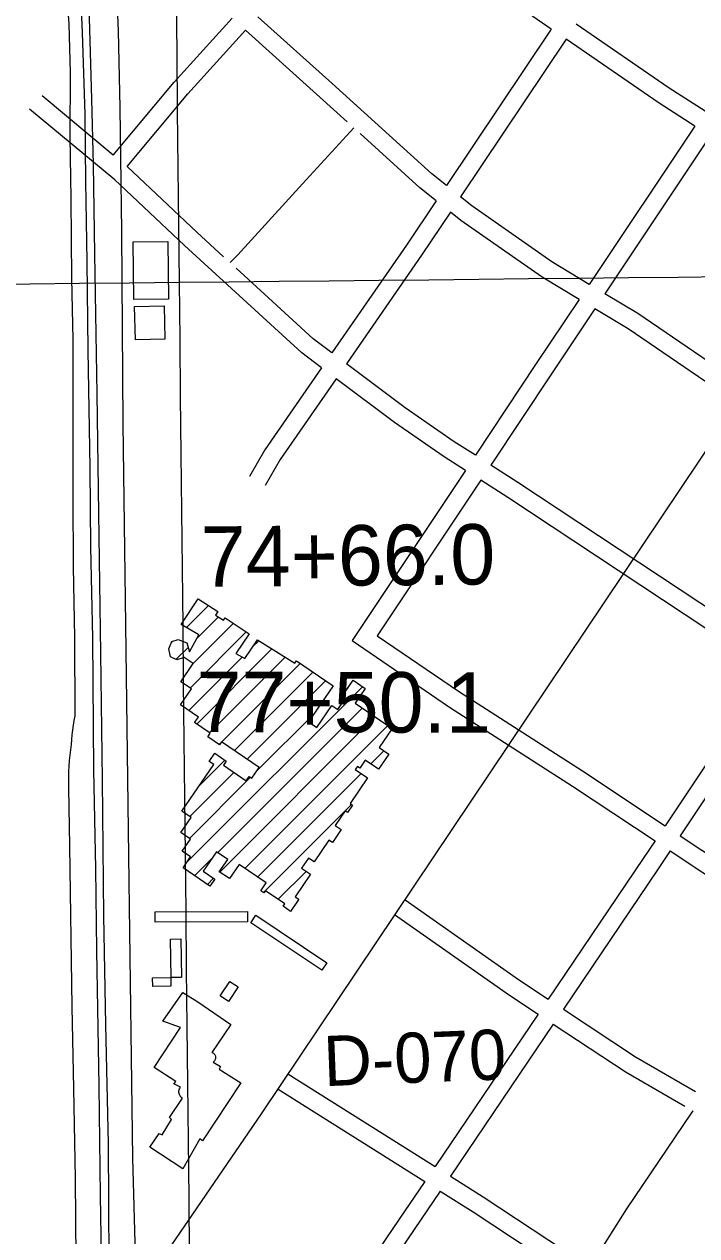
# Model space of a CAD drawing. Extents: x 3651524 to 3689615, y 505651 to 531377.
# Drawn here: x 3660662 to 3661774, y 521661 to 523666 of the extents above; entities that cross this region are included whole.
import ezdxf

# ---------------------------------------------------------------- set-up
doc = ezdxf.new("R2010")
doc.units = 0
for name, color, linetype in [('V-BLDG-OTLN', 7, 'Continuous'), ('V-GRID-MAJR', 7, 'Continuous'), ('V-RAIL-TRAK', 7, 'Continuous'), ('V-RIVR-RANG-IDEN', 7, 'Continuous'), ('V-ROAD-CNTR', 7, 'Continuous'), ('V-SURV-IDEN', 7, 'Continuous')]:
    doc.layers.add(name, color=color, linetype=linetype)

msp = doc.modelspace()

# ---------------------------------------------------------------- linework, layer by layer
at = {"layer": 'V-BLDG-OTLN'}
for p, q in [((3660930.25, 522667.432), (3660966.629, 522703.812)), ((3660940.957, 522607.429), (3661007.926, 522674.398)), ((3660947.036, 522648.864), (3660982.984, 522684.811)), ((3660936.162, 522567.278), (3661029.151, 522660.268)), ((3660905.354, 522642.537), (3660907.412, 522644.595)), ((3660912.74, 522614.567), (3660932.78, 522634.607)), ((3661040.092, 522635.853), (3661049.846, 522645.607)), ((3660934.234, 522529.996), (3661022.552, 522618.313)), ((3660947.236, 522507.642), (3661071.585, 522631.99)), ((3660968.25, 522493.3), (3661093.323, 522618.373)), ((3660988.43, 522478.125), (3661118.28, 522607.975)), ((3661009.443, 522463.783), (3661139.292, 522593.632)), ((3661030.457, 522449.441), (3661160.305, 522579.29)), ((3660930.849, 522279.123), (3661221.244, 522569.517)), ((3660982.092, 522295.01), (3661220.882, 522533.8)), ((3660985.322, 522262.885), (3661241.895, 522519.458)), ((3661045.955, 522429.584), (3661142.284, 522525.913)), ((3661026.568, 522268.776), (3661262.909, 522505.117)), ((3660983.921, 522473.616), (3660986.898, 522476.593)), ((3661234.878, 522441.73), (3661256.591, 522463.444)), ((3660951.529, 522405.869), (3660993.588, 522447.928)), ((3660934.93, 522318.559), (3661036.105, 522419.734)), ((3660935.626, 522354.61), (3661008.745, 522427.729)), ((3661047.58, 522254.433), (3661219.009, 522425.861)), ((3661192.678, 522364.176), (3661202.934, 522374.431)), ((3661057.399, 522228.896), (3661192.141, 522363.638)), ((3660943.722, 522256.641), (3660972.28, 522285.199)), ((3660964.735, 522242.298), (3660975.099, 522252.663)), ((3661081.547, 522217.689), (3661127.851, 522263.993))]:
    msp.add_line(p, q, dxfattribs=at)
for points in [[(3660899.25, 523306.151), (3660900.525, 523210.829), (3660843.259, 523210.063), (3660841.985, 523305.385)], [(3660893.224, 523199.71), (3660894.619, 523144.637), (3660845.84, 523143.405), (3660844.443, 523198.475)], [(3661112.07, 522612.213), (3661172.864, 522570.718), (3661132.212, 522511.156), (3661145.929, 522501.795), (3661170.777, 522538.2), (3661180.247, 522531.737), (3661189.623, 522545.475), (3661184.329, 522549.089), (3661205.571, 522580.213), (3661225.621, 522566.53), (3661208.874, 522541.995), (3661270.032, 522500.255), (3661248.622, 522468.883), (3661264.562, 522458.004), (3661247.551, 522433.08), (3661225.875, 522447.875), (3661217.042, 522434.934), (3661212.989, 522437.701), (3661209.388, 522432.427), (3661229.631, 522418.611), (3661200.576, 522376.041), (3661204.643, 522373.264), (3661196.611, 522361.492), (3661192.562, 522364.255), (3661176.018, 522340.017), (3661186.199, 522333.07), (3661171.613, 522311.701), (3661165.672, 522315.757), (3661141.061, 522279.697), (3661131.968, 522285.905), (3661120.456, 522269.04), (3661135.005, 522259.111), (3661109.675, 522221.997), (3661115.891, 522217.754), (3661102.19, 522197.677), (3661089.82, 522206.119), (3661092.579, 522210.16), (3661060.603, 522231.983), (3661058.148, 522228.385), (3661052.936, 522231.942), (3661061.705, 522244.791), (3661017.057, 522275.268), (3661001.205, 522252.043), (3660984.52, 522263.432), (3660998.453, 522283.845), (3660979.967, 522296.46), (3660958.027, 522264.317), (3660977.176, 522251.245), (3660969.058, 522239.348), (3660924.471, 522269.781), (3660936.97, 522288.088), (3660923.271, 522297.439), (3660936.81, 522317.276), (3660920.872, 522328.153), (3660937.881, 522353.071), (3660922.607, 522363.493), (3660975.185, 522440.529), (3660967.561, 522445.733), (3660976.854, 522459.35), (3660995.841, 522446.39), (3660991.254, 522439.669), (3661029.048, 522413.87), (3661034.02, 522421.157), (3661038.239, 522418.277), (3661050.275, 522435.915), (3660988.098, 522478.351), (3660984.565, 522473.176), (3660965.32, 522486.312), (3660969.504, 522492.444), (3660943.701, 522510.054), (3660949.979, 522519.25), (3660920.446, 522539.406), (3660938.42, 522565.737), (3660920.739, 522577.804), (3660941.168, 522607.738), (3660926.562, 522617.705), (3660914.04, 522613.917), (3660903.802, 522619.037), (3660900.89, 522632.113), (3660906.043, 522644.145), (3660916.434, 522647.557), (3660930.705, 522641.917), (3660934.932, 522627.022), (3660950.706, 522655.485), (3660921.366, 522672.621), (3660949.507, 522714.789), (3660981.925, 522694.006), (3660978.222, 522687.784), (3660991.549, 522679.465), (3660994.314, 522683.459), (3661033.82, 522657.16), (3661011.683, 522624.314), (3661026.805, 522615.965), (3661047.564, 522647.037), (3661109.403, 522608.301)], [(3661031.151, 522180.699), (3660878.436, 522179.804), (3660878.337, 522196.727), (3661031.051, 522197.62)], [(3661154.131, 522100.381), (3661036.507, 522178.809), (3661044.809, 522191.261), (3661162.438, 522112.832)], [(3660905.111, 522088.164), (3660903.542, 522151.966), (3660920.616, 522152.383), (3660922.183, 522088.582)], [(3660904.406, 522073.806), (3660874.309, 522073.437), (3660874.133, 522087.966), (3660904.23, 522088.328)], [(3661015.768, 522072.735), (3660999.626, 522048.769), (3660985.991, 522057.952), (3661002.133, 522081.92)], [(3661003.802, 522010.578), (3660972.283, 521964.49), (3660973.582, 521963.914), (3660974.772, 521963.142), (3660975.824, 521962.194), (3660976.717, 521961.09), (3660977.428, 521959.859), (3660977.934, 521958.534), (3660978.229, 521957.144), (3660978.3, 521955.726), (3660978.149, 521954.313), (3660977.778, 521952.941), (3660977.198, 521951.645), (3660976.422, 521950.455), (3660975.47, 521949.402), (3660974.364, 521948.511), (3660986.634, 521941.208), (3660984.19, 521936.528), (3661019.811, 521914.052), (3660956.71, 521818.33), (3660952.041, 521821.365), (3660924.002, 521771.673), (3660869.721, 521807.467), (3660884.885, 521830.229), (3660890.156, 521827.773), (3660905.371, 521853.486), (3660901.879, 521856.499), (3660923.707, 521888.589), (3660922.349, 521889.496), (3660921.124, 521890.579), (3660920.059, 521891.816), (3660919.166, 521893.184), (3660918.468, 521894.661), (3660917.972, 521896.216), (3660917.69, 521897.825), (3660917.624, 521899.458), (3660917.784, 521901.084), (3660918.157, 521902.675), (3660918.738, 521904.201), (3660919.521, 521905.634), (3660920.489, 521906.949), (3660909.367, 521912.46), (3660912.392, 521916.54), (3660876.781, 521939.604), (3660920.104, 522005.564), (3660891.359, 522016.11), (3660924.077, 522063.359), (3660948.791, 522048.202)]]:
    msp.add_lwpolyline(points, close=True, dxfattribs=at)
at = {"layer": 'V-GRID-MAJR'}
for points in [[(3661045.474, 511119.283), (3660982.023, 517177.978), (3660918.553, 523238.605), (3660855.082, 529299.245), (3660855.062, 529301.164)], [(3655639.78, 523183.706), (3660918.553, 523238.605), (3666197.317, 523294.271), (3671476.073, 523350.705), (3676754.821, 523407.907), (3682033.561, 523465.877), (3687312.292, 523524.615)]]:
    msp.add_spline(points, degree=3, dxfattribs=at)
at = {"layer": 'V-RAIL-TRAK'}
for points in [[(3660802.488, 521616.582), (3660801.238, 521813.224), (3660797.038, 522009.92), (3660793.737, 522190.656), (3660791.218, 522415.664), (3660788.418, 522624.734), (3660785.434, 522856.834), (3660782.425, 523054.099), (3660778.839, 523285.622), (3660776.726, 523433.27), (3660773.914, 523541.374), (3660768.47, 523734.547)], [(3660755.14, 523715.298), (3660757.565, 523652.079), (3660762.261, 523516.782), (3660763.24, 523405.168), (3660765.626, 523272.865), (3660767.17, 523126.404), (3660770.221, 522931.5), (3660771.446, 522800.399), (3660774.7, 522650.367), (3660776.732, 522431.272), (3660779.767, 522268.843), (3660781.5, 522133.009), (3660785.211, 521908.571), (3660787.33, 521727.856), (3660790.837, 521525.267)]]:
    msp.add_lwpolyline(points, dxfattribs=at)
at = {"layer": 'V-ROAD-CNTR'}
for points in [[(3660141.295, 529270.676), (3660140.146, 529257.885), (3660207.54, 528672.889), (3660264.536, 528198.301), (3660307.434, 527853.775), (3660381.584, 527230.666), (3660444.851, 526759.634), (3660523.843, 526091.959), (3660593.844, 525547.214), (3660619.118, 525319.853), (3660656.441, 525032.649), (3660719.252, 524520.83), (3660759.714, 524185.351), (3660783.113, 524013.914), (3660804.031, 523834.787), (3660814.113, 523733.801), (3660817.382, 523654.494), (3660819.82, 523527.387), (3660822.74, 523322.401), (3660825.188, 523004.512), (3660829.644, 522672.085), (3660834.768, 522247.179), (3660840.69, 521789.439), (3660851.979, 521389.387)], [(3662939.923, 524671.627), (3662283.158, 523697.88), (3661053.666, 521862.612), (3660883.673, 521614.704), (3660848.114, 521559.045)], [(3660627.349, 524614.538), (3660645.482, 524433.343), (3660664.08, 524278.576), (3660684.66, 524104.758), (3660707.487, 523926.728), (3660727.85, 523766.828), (3660735.809, 523666.046), (3660737.628, 523585.316), (3660737.607, 523479.111), (3660739.051, 523377.053), (3660739.96, 523244.858), (3660742.354, 523144.177), (3660742.387, 523014.782), (3660742.412, 522884.922), (3660743.12, 522767.574), (3660745.228, 522650.664), (3660745.723, 522521.259)], [(3661533.139, 523657.593), (3661502.758, 523678.468), (3661291.389, 523869.022), (3661255.044, 523902.937)], [(3661359.976, 523398.533), (3661335.66, 523417.953), (3661170.916, 523567.305), (3661048.106, 523677.717)], [(3660809.055, 523449.183), (3660909.645, 523569.838), (3661005.63, 523675.563)], [(3661533.138, 523657.594), (3661359.976, 523398.533)], [(3661787.602, 523521.798), (3661728.113, 523560.028), (3661574.539, 523665.547)], [(3660832.073, 523429.944), (3660932.283, 523550.142), (3661027.941, 523655.506)], [(3661195.885, 523504.175), (3661150.812, 523545.037), (3661027.941, 523655.506)], [(3661557.867, 523640.605), (3661383.501, 523379.744)], [(3661770.938, 523496.846), (3661711.505, 523535.04), (3661557.867, 523640.603)], [(3660809.055, 523449.183), (3660691.692, 523546.851)], [(3660811.763, 523407.9), (3660670.775, 523525.229)], [(3661770.938, 523496.848), (3661596.141, 523235.133)], [(3661206.71, 523494.362), (3661122.236, 523401.5), (3661015.115, 523283.946), (3661002.242, 523271.186)], [(3661343.244, 523373.502), (3661316.206, 523395.097), (3661217.445, 523484.63)], [(3661796.179, 523480.627), (3661621.898, 523219.686)], [(3660991.637, 523280.91), (3660947.14, 523321.705), (3660832.073, 523429.944)], [(3661153.647, 523097.107), (3661120.718, 523121.866), (3660926.724, 523299.721), (3660811.08, 523408.504)], [(3661596.141, 523235.133), (3661534.383, 523272.171), (3661401.837, 523365.099), (3661383.501, 523379.744)], [(3661343.244, 523373.502), (3661294.255, 523300.211), (3661170.737, 523121.793)], [(3661366.77, 523354.713), (3661319.061, 523283.337), (3661194.734, 523103.75)], [(3661579.458, 523210.157), (3661518.037, 523246.993), (3661383.847, 523341.073), (3661366.77, 523354.713)], [(3661170.737, 523121.792), (3661139.914, 523144.966), (3661012.258, 523262.004)], [(3662097.596, 522903.078), (3662048.074, 522933.12), (3661676.526, 523186.923), (3661621.898, 523219.686)], [(3661579.458, 523210.157), (3661508.571, 523104.021), (3661407.952, 522952.433)], [(3661605.217, 523194.708), (3661533.543, 523087.395), (3661433.235, 522936.277)], [(3662080.936, 522878.096), (3662031.822, 522907.89), (3661660.336, 523161.651), (3661605.217, 523194.708)], [(3661153.648, 523097.108), (3661059.752, 522961.478), (3661034.426, 522917.174)], [(3661407.952, 522952.433), (3661372.866, 522974.855), (3661291.726, 523030.823), (3661194.734, 523103.749)], [(3661177.644, 523079.065), (3661085.154, 522945.466), (3661060.47, 522902.286)], [(3661391.359, 522927.434), (3661356.266, 522949.861), (3661274.188, 523006.477), (3661177.644, 523079.065)], [(3661910.688, 522622.809), (3661880.085, 522641.509), (3661478.155, 522907.571), (3661433.235, 522936.277)], [(3661391.359, 522927.434), (3661204.371, 522645.726), (3661364.99, 522535.723), (3661568.47, 522404.949), (3661705.046, 522314.45)], [(3661416.642, 522911.278), (3661245.716, 522653.77), (3661381.58, 522560.723), (3661584.866, 522430.073), (3661721.691, 522339.409)], [(3661894.03, 522597.83), (3661863.979, 522616.193), (3661461.797, 522882.421), (3661416.642, 522911.278)], [(3661894.029, 522597.831), (3661721.691, 522339.408)], [(3661919.649, 522582.177), (3661746.698, 522322.837)], [(3660745.723, 522521.259), (3660744.148, 522513.477), (3660742.807, 522505.651), (3660741.699, 522497.791), (3660740.827, 522489.9), (3660740.19, 522481.987), (3660739.788, 522474.059), (3660738.432, 522465.152), (3660737.304, 522456.214), (3660736.399, 522447.25), (3660735.721, 522438.268), (3660735.268, 522429.269), (3660735.043, 522420.264), (3660735.045, 522411.257), (3660735.272, 522402.252), (3660736.814, 522305.758), (3660740.464, 522039.946), (3660743.174, 521904.475), (3660746.123, 521756.476), (3660746.985, 521621.503)], [(3661705.046, 522314.449), (3661685.476, 522285.103), (3661528.387, 522052.765)], [(3661746.698, 522322.838), (3661959.795, 522181.634)], [(3661730.055, 522297.878), (3661710.382, 522268.379), (3661553.395, 522036.194)], [(3661730.054, 522297.879), (3661942.839, 522156.881)], [(3661291.545, 522217.113), (3661481.093, 522084.102), (3661528.387, 522052.765)], [(3661274.313, 522192.557), (3661464.189, 522059.314), (3661511.582, 522027.911)], [(3661553.395, 522036.194), (3661672.864, 521957.034), (3661771.971, 521899.726)], [(3661511.582, 522027.911), (3661341.133, 521775.815)], [(3661536.592, 522011.34), (3661366.528, 521759.813)], [(3661536.592, 522011.34), (3661657.056, 521931.52), (3661754.373, 521875.248)], [(3661097.755, 521929.177), (3661341.133, 521775.815)], [(3661081.761, 521903.795), (3661324.321, 521750.948)], [(3661767.168, 521867.725), (3661764.462, 521863.81), (3661657.749, 521705.682), (3661596.6, 521608.65)], [(3661366.528, 521759.813), (3661420.693, 521725.682), (3661584.422, 521617.402)], [(3661324.321, 521750.948), (3661281.971, 521688.313), (3661138.007, 521475.952)], [(3661349.716, 521734.948), (3661306.813, 521671.495), (3661163.006, 521459.363)], [(3661349.716, 521734.948), (3661404.421, 521700.476), (3661568.543, 521591.938)]]:
    msp.add_lwpolyline(points, dxfattribs=at)

# ---------------------------------------------------------------- texts
at = {"layer": 'V-RIVR-RANG-IDEN'}
msp.add_text('D-070', height=83, rotation=2.224326, dxfattribs=at).set_placement((3661158.153, 521908.446))
at = {"layer": 'V-SURV-IDEN'}
for s, rotation, p in [('74+66.0', 0.501032, (3660954.043, 522734.557)), ('77+50.1', 359.84, (3660946.559, 522494.512))]:
    msp.add_text(s, height=100, rotation=rotation, dxfattribs=at).set_placement(p)

doc.saveas('drawing.dxf')
